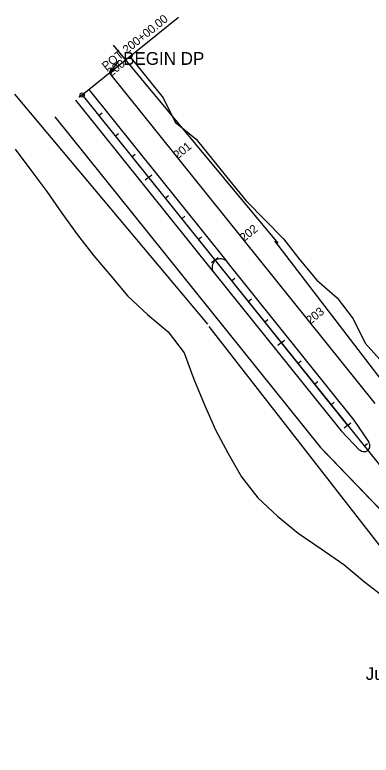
# Model space of a CAD drawing. Extents: x 2717836 to 2719883, y 337327 to 339806.
# Drawn here: x 2717836 to 2718173, y 339108 to 339806 of the extents above; entities that cross this region are included whole.
import ezdxf

# ---------------------------------------------------------------- set-up
doc = ezdxf.new("R2010")
doc.units = 0
for name, color, linetype in [('Level 1', 7, 'Continuous'), ('Level 2', 7, 'Continuous'), ('Level 22', 7, 'Continuous'), ('Level 23', 7, 'Continuous'), ('Level 3', 7, 'Continuous'), ('Level 31', 7, 'Continuous'), ('Level 5', 7, 'Continuous'), ('Level 60', 7, 'Continuous'), ('Level 62', 7, 'Continuous'), ('Level 8', 7, 'Continuous')]:
    doc.layers.add(name, color=color, linetype=linetype)

msp = doc.modelspace()

# ---------------------------------------------------------------- linework, layer by layer
at = {"layer": 'Level 1'}
msp.add_line((2717900.04, 339730.6), (2718401.03, 339107.9), dxfattribs=at)
at = {"layer": 'Level 22'}
for p, q in [((2717945.23, 339766.96), (2717960.9, 339747.48)), ((2717960.9, 339747.48), (2717976.57, 339728)), ((2717976.57, 339728), (2717987.99, 339705.1)), ((2717987.99, 339705.1), (2718007.71, 339688.88)), ((2718007.71, 339688.88), (2718023.59, 339669.57)), ((2717836.67, 339679.61), (2717851.67, 339659.6)), ((2718023.59, 339669.57), (2718039.26, 339650.09)), ((2717851.67, 339659.6), (2717866.61, 339639.53)), ((2718039.26, 339650.09), (2718054.93, 339630.61)), ((2717866.61, 339639.53), (2717881.03, 339619.05)), ((2718054.93, 339630.61), (2718072.59, 339612.73)), ((2717881.03, 339619.05), (2717895.6, 339598.68)), ((2718072.59, 339612.73), (2718090.16, 339594.78)), ((2717895.6, 339598.68), (2717911.02, 339579)), ((2718090.16, 339594.78), (2718105.6, 339575.11)), ((2717911.02, 339579), (2717927.26, 339559.98)), ((2718105.6, 339575.11), (2718121.64, 339555.93)), ((2717927.26, 339559.98), (2717943.25, 339540.76)), ((2718121.64, 339555.93), (2718140.93, 339539.36)), ((2717943.25, 339540.76), (2717961.83, 339523.62)), ((2718140.93, 339539.36), (2718155.89, 339519.32)), ((2717961.83, 339523.62), (2717981.21, 339507.13)), ((2718155.89, 339519.32), (2718167.42, 339496.5)), ((2717981.21, 339507.13), (2717996.41, 339487.27)), ((2718167.42, 339496.5), (2718184.11, 339477.85)), ((2717996.41, 339487.27), (2718005.51, 339462.5)), ((2718005.51, 339462.5), (2718015.51, 339438.46)), ((2718015.51, 339438.46), (2718025.92, 339414.75)), ((2718025.92, 339414.75), (2718038.12, 339392.48)), ((2718038.12, 339392.48), (2718050.55, 339370.39)), ((2718050.55, 339370.39), (2718065.89, 339350.65)), ((2718065.89, 339350.65), (2718084.42, 339333.47)), ((2718084.42, 339333.47), (2718104.05, 339317.18)), ((2718104.05, 339317.18), (2718125.67, 339302.48)), ((2718125.67, 339302.48), (2718147.31, 339287.81)), ((2718147.31, 339287.81), (2718166.86, 339271.45)), ((2718166.86, 339271.45), (2718187.13, 339255.67))]:
    msp.add_line(p, q, dxfattribs=at)
at = {"layer": 'Level 23'}
for p, q in [((2718085.16, 339590.77), (2717929.82, 339777.44)), ((2718018.9, 339514.3), (2717836.44, 339731.4)), ((2718222.31, 339410.32), (2718081.98, 339592.89)), ((2718281.94, 339176.11), (2718019.96, 339512.18))]:
    msp.add_line(p, q, dxfattribs=at)
at = {"layer": 'Level 3'}
for p, q in [((2717925.75, 339751.29), (2718176.49, 339439.63)), ((2717906.28, 339735.62), (2718036.66, 339573.55)), ((2717893.81, 339725.59), (2718024.19, 339563.53)), ((2717874.33, 339709.91), (2718125.07, 339398.26))]:
    msp.add_line(p, q, dxfattribs=at)
for points in [[(2718125.07, 339398.26), (2718125.54, 339397.77), (2718126.01, 339397.28), (2718126.48, 339396.79), (2718126.95, 339396.31), (2718127.43, 339395.82), (2718127.89, 339395.33), (2718128.37, 339394.84), (2718128.84, 339394.35), (2718129.31, 339393.86), (2718129.78, 339393.37), (2718130.25, 339392.89), (2718130.72, 339392.4), (2718131.19, 339391.91), (2718131.66, 339391.42), (2718132.14, 339390.93), (2718132.6, 339390.45), (2718133.08, 339389.95), (2718133.55, 339389.47), (2718134.02, 339388.98), (2718134.49, 339388.5), (2718134.96, 339388), (2718135.43, 339387.52), (2718135.9, 339387.03), (2718136.37, 339386.54), (2718136.84, 339386.05), (2718137.32, 339385.56), (2718137.78, 339385.08), (2718138.26, 339384.58), (2718138.72, 339384.1), (2718139.2, 339383.61), (2718139.67, 339383.12), (2718140.14, 339382.63), (2718140.61, 339382.14), (2718141.08, 339381.66), (2718141.55, 339381.17), (2718142.02, 339380.68), (2718142.49, 339380.19), (2718142.97, 339379.7), (2718143.44, 339379.22), (2718143.91, 339378.72), (2718144.38, 339378.24), (2718144.85, 339377.75), (2718145.32, 339377.26), (2718145.79, 339376.77), (2718146.26, 339376.28), (2718146.73, 339375.8), (2718147.21, 339375.31), (2718147.67, 339374.82), (2718148.15, 339374.33), (2718148.61, 339373.85), (2718149.09, 339373.35), (2718149.56, 339372.86), (2718150.03, 339372.38), (2718150.5, 339371.89), (2718150.97, 339371.4), (2718151.44, 339370.91), (2718151.91, 339370.43), (2718152.38, 339369.94), (2718152.85, 339369.45), (2718153.33, 339368.96), (2718153.8, 339368.47), (2718154.27, 339367.98), (2718154.74, 339367.49), (2718155.21, 339367.01), (2718155.68, 339366.52), (2718156.15, 339366.03), (2718156.62, 339365.54), (2718157.1, 339365.05), (2718157.56, 339364.57), (2718158.04, 339364.07), (2718158.5, 339363.59), (2718158.98, 339363.1), (2718159.45, 339362.61), (2718159.92, 339362.12)], [(2718159.92, 339362.12), (2718160.39, 339361.63), (2718160.86, 339361.15), (2718161.33, 339360.66), (2718161.8, 339360.17), (2718162.27, 339359.68), (2718162.74, 339359.2), (2718163.22, 339358.7), (2718163.69, 339358.21), (2718164.16, 339357.73), (2718164.63, 339357.24), (2718165.1, 339356.75), (2718165.57, 339356.26), (2718166.04, 339355.78), (2718166.51, 339355.29), (2718166.99, 339354.79), (2718167.45, 339354.31), (2718167.93, 339353.82), (2718168.39, 339353.33), (2718168.87, 339352.84), (2718169.34, 339352.36), (2718169.81, 339351.87), (2718170.28, 339351.38), (2718170.75, 339350.89), (2718171.22, 339350.4), (2718171.69, 339349.92), (2718172.16, 339349.42), (2718172.63, 339348.94), (2718173.11, 339348.45), (2718173.57, 339347.96), (2718174.05, 339347.47), (2718174.52, 339346.98), (2718174.99, 339346.5), (2718175.46, 339346.01), (2718175.93, 339345.52), (2718176.4, 339345.03), (2718176.87, 339344.55), (2718177.34, 339344.05), (2718177.82, 339343.56), (2718178.28, 339343.08), (2718178.76, 339342.59), (2718179.23, 339342.1), (2718179.7, 339341.61), (2718180.17, 339341.13), (2718180.64, 339340.64), (2718181.11, 339340.14), (2718181.58, 339339.66), (2718182.05, 339339.17), (2718182.52, 339338.68), (2718183, 339338.19), (2718183.46, 339337.71), (2718183.94, 339337.22), (2718184.41, 339336.73), (2718184.88, 339336.24), (2718185.35, 339335.75), (2718185.82, 339335.27), (2718186.29, 339334.77), (2718186.76, 339334.29), (2718187.23, 339333.8), (2718187.7, 339333.32), (2718188.17, 339332.82), (2718188.65, 339332.33), (2718189.12, 339331.85), (2718189.59, 339331.36), (2718190.06, 339330.87), (2718190.53, 339330.38), (2718191, 339329.9), (2718191.47, 339329.41), (2718191.94, 339328.91), (2718192.41, 339328.43), (2718192.89, 339327.94), (2718193.35, 339327.45), (2718193.83, 339326.96), (2718194.77, 339325.99)]]:
    msp.add_spline(points, degree=3, dxfattribs=at)
at = {"layer": 'Level 31'}
for p, q in [((2717901.6, 339731.85), (2717991.22, 339803.96)), ((2717900.04, 339730.6), (2717903.16, 339733.11)), ((2717900.04, 339730.6), (2717896.93, 339728.09)), ((2717915.71, 339711.12), (2717918.83, 339713.63)), ((2717931.38, 339691.64), (2717934.5, 339694.15)), ((2717947.06, 339672.17), (2717950.17, 339674.67)), ((2717962.73, 339652.69), (2717959.61, 339650.18)), ((2717962.73, 339652.69), (2717965.84, 339655.19)), ((2717978.4, 339633.21), (2717981.51, 339635.72)), ((2717994.07, 339613.73), (2717997.19, 339616.24)), ((2718009.74, 339594.25), (2718012.86, 339596.76)), ((2718025.41, 339574.77), (2718022.3, 339572.27)), ((2718025.41, 339574.77), (2718028.53, 339577.28)), ((2718041.08, 339555.29), (2718044.2, 339557.8)), ((2718056.75, 339535.82), (2718059.87, 339538.32)), ((2718072.43, 339516.34), (2718075.54, 339518.84)), ((2718088.1, 339496.86), (2718084.98, 339494.35)), ((2718088.1, 339496.86), (2718091.21, 339499.37)), ((2718103.77, 339477.38), (2718106.88, 339479.89)), ((2718119.44, 339457.9), (2718122.56, 339460.41)), ((2718135.11, 339438.42), (2718138.23, 339440.93)), ((2718150.78, 339418.94), (2718147.67, 339416.44)), ((2718150.78, 339418.94), (2718153.9, 339421.45)), ((2718166.45, 339399.47), (2718169.57, 339401.97))]:
    msp.add_line(p, q, dxfattribs=at)
msp.add_circle((2717900.04, 339730.6), 2, dxfattribs=at)
at = {"layer": 'Level 5'}
for p, q in [((2718157.02, 339423.96), (2718036.92, 339573.23)), ((2718024.45, 339563.2), (2718144.55, 339413.93)), ((2718171.27, 339403.02), (2718157.02, 339423.96)), ((2718144.55, 339413.93), (2718161.94, 339395.54))]:
    msp.add_line(p, q, dxfattribs=at)
for centre, radius, start, end in [((2718030.72, 339568.17), 8, 39.29609, 218.34012), ((2718166.29, 339399.67), 5.5, 223.33628, 34.24903)]:
    msp.add_arc(centre, radius, start, end, dxfattribs=at)
at = {"layer": 'Level 62'}
for q in [(2717935.07, 339763.14), (2717927.65, 339756.43), (2717930.91, 339754.26)]:
    msp.add_line((2717925.75, 339751.29), q, dxfattribs=at)
at = {"layer": 'Level 8'}
for p, q in [((2717900.04, 339730.6), (2718042.66, 339553.34)), ((2718042.66, 339553.34), (2718150.78, 339418.94))]:
    msp.add_line(p, q, dxfattribs=at)

# ---------------------------------------------------------------- texts
at = {"layer": 'Level 2'}
msp.add_text('Junction #2', height=12, dxfattribs=at).set_placement((2718167.94, 339178.89))
at = {"layer": 'Level 31'}
for s, p in [('POT 200+00.00', (2717922.78, 339753.39)), ('200', (2717927.48, 339747.54)), ('201', (2717990.17, 339669.63)), ('202', (2718052.85, 339591.72)), ('203', (2718115.54, 339513.8))]:
    msp.add_text(s, height=8, rotation=38.81809, dxfattribs=at).set_placement(p)
at = {"layer": 'Level 60'}
msp.add_text('BEGIN DP', height=12, dxfattribs=at).set_placement((2717938.76, 339759.02))

doc.saveas('drawing.dxf')
